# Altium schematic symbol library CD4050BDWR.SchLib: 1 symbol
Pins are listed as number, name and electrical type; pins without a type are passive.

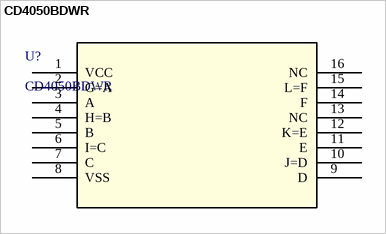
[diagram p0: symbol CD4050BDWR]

## CD4050BDWR
designator U?
6-ch, 3-V to 18-V buffers 16-SOIC -55 to 125; Manufacturer_Name: Texas Instruments
footprint DW16
pins: 1 VCC (power), 2 G=A, 3 A, 4 H=B, 5 B, 6 I=C, 7 C, 8 VSS (power), 9 D, 10 J=D, 11 E, 12 K=E, 13 NC, 14 F, 15 L=F, 16 NC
